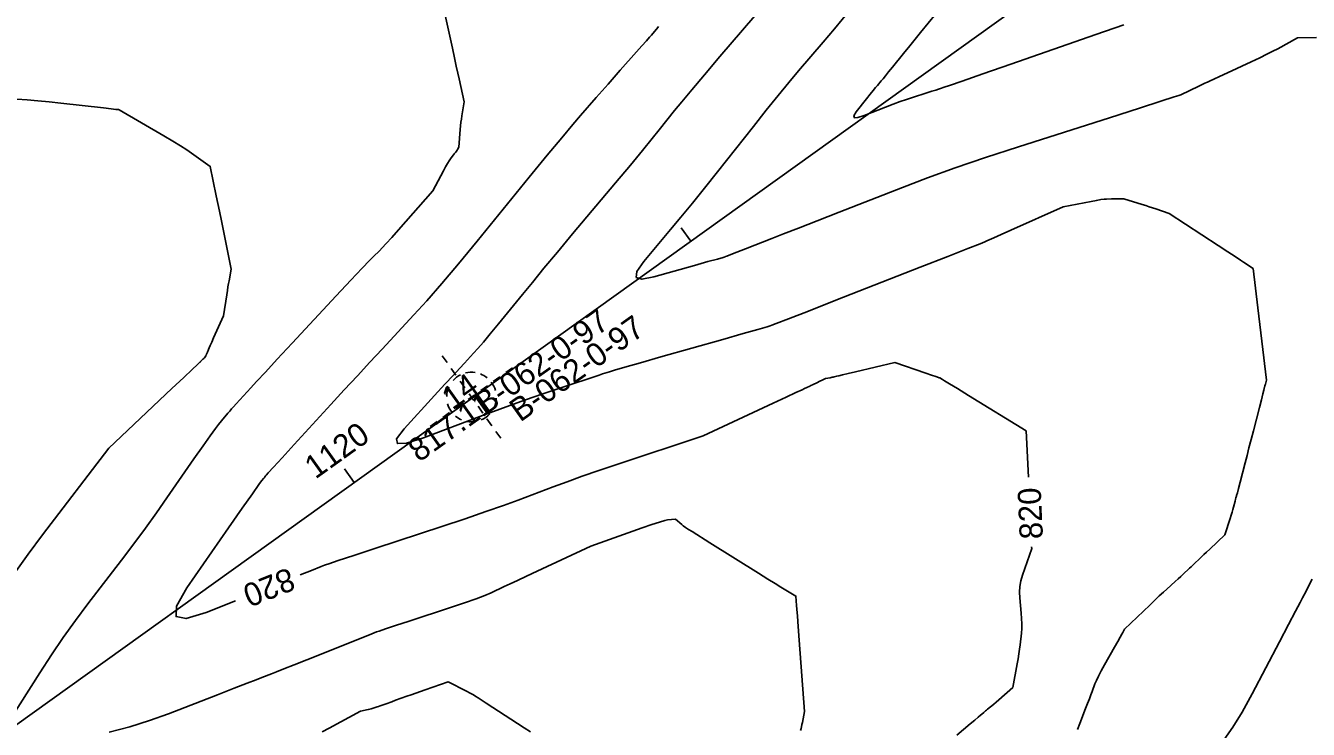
# Model space of a CAD drawing. Extents: x 2079879 to 2092887, y 778083 to 784051.
# Drawn here: x 2083948 to 2084103, y 780967 to 781052 of the extents above; entities that cross this region are included whole.
import ezdxf

# ---------------------------------------------------------------- set-up
doc = ezdxf.new("R2010")
doc.units = 0
for name, color, linetype in [('DT_X_Contour_Major', 7, 'Continuous'), ('DT_X_Contour_Minor', 7, 'Continuous'), ('GE_X_CL_20', 7, 'Continuous'), ('GT_Historic_Soil_Boring', 7, 'Continuous'), ('GT_Project_Text', 7, 'Continuous'), ('SV_X_Text_Comment', 7, 'Continuous'), ('SV_X_Text_Elevation', 7, 'Continuous'), ('SV_X_Text_Name', 7, 'Continuous')]:
    doc.layers.add(name, color=color, linetype=linetype)

msp = doc.modelspace()

# ---------------------------------------------------------------- linework, layer by layer
at = {"layer": 'DT_X_Contour_Major'}
for points in [[(2084024.47, 781051.89), (2084024.38, 781051.77), (2084023.62, 781050.86), (2084023.38, 781050.59), (2084023.01, 781050.16), (2084022.48, 781049.57), (2084021.82, 781048.81), (2084019.85, 781046.6), (2084019.12, 781045.77), (2084018.39, 781044.94), (2084017.67, 781044.12), (2084016.95, 781043.31), (2084015.04, 781041.14), (2084014.12, 781040.06), (2084012.78, 781038.46), (2084011.03, 781036.35), (2084008.87, 781033.71), (2084002.56, 781025.97), (2084000.31, 781023.24), (2083998.29, 781020.85), (2083996.5, 781018.79), (2083994.94, 781017.08), (2083991.1, 781012.95), (2083989.63, 781011.37), (2083988.11, 781009.72), (2083986.53, 781008.01), (2083984.9, 781006.24), (2083980.47, 781001.41), (2083979.02, 780999.83), (2083977.98, 780998.69), (2083977.34, 780998), (2083977.12, 780997.75), (2083977.07, 780997.69), (2083977.04, 780997.65), (2083976.98, 780997.59), (2083976.91, 780997.5), (2083976.81, 780997.38), (2083976.52, 780997.04), (2083976.19, 780996.59), (2083975.42, 780995.49), (2083974.2, 780993.74), (2083972.54, 780991.35), (2083967.52, 780984.12), (2083966.26, 780981.9), (2083966.22, 780980.66), (2083967.42, 780980.41), (2083969.85, 780981.14), (2083973.4, 780982.56)], [(2083981.2, 780985.68), (2083982.55, 780986.22), (2083983.72, 780986.69), (2083984.14, 780986.85), (2083984.24, 780986.9), (2083984.66, 780987.03), (2083985.8, 780987.41), (2083987.69, 780988.04), (2083990.32, 780988.9), (2083998.32, 780991.53), (2084001.14, 780992.47), (2084003.61, 780993.32), (2084005.74, 780994.06), (2084007.51, 780994.71), (2084011.76, 780996.32), (2084013.44, 780996.94), (2084015.27, 780997.59), (2084017.27, 780998.28), (2084019.43, 780999), (2084029.87, 781002.46), (2084038.31, 781006.4), (2084039.91, 781007.14), (2084041.07, 781007.69), (2084041.81, 781008.03), (2084042.12, 781008.17), (2084042.37, 781008.29), (2084042.45, 781008.33), (2084042.52, 781008.36), (2084042.56, 781008.38), (2084042.58, 781008.39), (2084042.62, 781008.41), (2084042.66, 781008.43), (2084042.75, 781008.47), (2084042.89, 781008.54), (2084043.08, 781008.64), (2084043.66, 781008.92), (2084043.86, 781009.02), (2084044.03, 781009.1), (2084044.16, 781009.16), (2084044.26, 781009.21), (2084044.65, 781009.38), (2084045.22, 781009.49), (2084045.34, 781009.52), (2084045.46, 781009.54), (2084045.58, 781009.57), (2084045.7, 781009.6), (2084046.01, 781009.68), (2084046.24, 781009.73), (2084046.69, 781009.84), (2084047.37, 781010), (2084048.27, 781010.22), (2084053.02, 781011.34), (2084056.75, 781010.05), (2084057.46, 781009.81), (2084057.96, 781009.64), (2084058.28, 781009.53), (2084058.39, 781009.49), (2084058.47, 781009.47), (2084058.77, 781009.28), (2084059.01, 781009.13), (2084059.61, 781008.76), (2084060.58, 781008.17), (2084061.9, 781007.36), (2084068.89, 781003.06), (2084069.16, 780997.47)], [(2084069.54, 780989.08), (2084069.55, 780988.86), (2084068.44, 780985.66), (2084068.24, 780984.98), (2084068.12, 780984.29), (2084068.07, 780983.6), (2084068.1, 780982.92), (2084068.28, 780981.08), (2084068.33, 780980.41), (2084068.35, 780979.78), (2084068.34, 780979.2), (2084068.3, 780978.65), (2084068.16, 780977.24), (2084068.09, 780976.71), (2084068.01, 780976.15), (2084067.92, 780975.56), (2084067.81, 780974.96), (2084067.26, 780972.1), (2084065.58, 780970.62), (2084065.25, 780970.33), (2084064.97, 780970.09), (2084064.75, 780969.9), (2084064.59, 780969.76), (2084064.22, 780969.46), (2084064.09, 780969.36), (2084063.97, 780969.26), (2084063.86, 780969.17), (2084063.76, 780969.09), (2084063.51, 780968.89), (2084063.35, 780968.76), (2084063.07, 780968.51), (2084062.66, 780968.16), (2084062.12, 780967.7), (2084060.51, 780966.33)]]:
    msp.add_lwpolyline(points, dxfattribs=at)
at = {"layer": 'DT_X_Contour_Minor'}
for points in [[(2083998.32, 781055.1), (2083999.58, 781049.26), (2083999.83, 781048.1), (2084000.04, 781047.09), (2084000.23, 781046.25), (2084000.38, 781045.57), (2084000.99, 781042.78), (2084000.72, 781041.1), (2084000.67, 781040.72), (2084000.62, 781040.33), (2084000.57, 781039.91), (2084000.53, 781039.47), (2084000.36, 781037.34), (2084000.2, 781037.05), (2084000.15, 781036.97), (2084000.07, 781036.85), (2083999.95, 781036.69), (2083999.81, 781036.5), (2083999.37, 781035.93), (2083999.2, 781035.68), (2083998.99, 781035.35), (2083998.76, 781034.94), (2083998.5, 781034.46), (2083997.2, 781032.05), (2083993.06, 781027.33), (2083992.25, 781026.41), (2083991.6, 781025.68), (2083991.1, 781025.15), (2083990.76, 781024.8), (2083990.07, 781024.14), (2083989.59, 781023.66), (2083988.68, 781022.7), (2083987.33, 781021.27), (2083985.56, 781019.36), (2083980.24, 781013.65), (2083978.43, 781011.71), (2083977, 781010.17), (2083975.93, 781009.02), (2083975.25, 781008.28), (2083973.91, 781006.82), (2083973.47, 781006.33), (2083973.13, 781005.97), (2083972.92, 781005.73), (2083972.81, 781005.61), (2083972.69, 781005.46), (2083972.61, 781005.37), (2083972.48, 781005.22), (2083972.3, 781005), (2083972.06, 781004.71), (2083971.35, 781003.86), (2083970.96, 781003.36), (2083970.33, 781002.49), (2083969.47, 781001.27), (2083968.36, 780999.69), (2083965.09, 780994.98), (2083963.83, 780993.18), (2083962.5, 780991.34), (2083961.09, 780989.44), (2083959.61, 780987.48), (2083955.56, 780982.19), (2083954.06, 780980.19), (2083952.59, 780978.13), (2083951.16, 780976.02), (2083949.76, 780973.86), (2083946.07, 780968.04)], [(2084037.35, 781054.64), (2084031.89, 781048.27), (2084030.02, 781046.07), (2084028.48, 781044.24), (2084027.28, 781042.8), (2084026.42, 781041.74), (2084024.57, 781039.41), (2084023.72, 781038.35), (2084022.56, 781036.93), (2084021.08, 781035.16), (2084019.29, 781033.02), (2084014.1, 781026.84), (2084012.27, 781024.65), (2084010.64, 781022.7), (2084009.24, 781021), (2084008.05, 781019.55), (2084005.16, 781016.01), (2084004.16, 781014.8), (2084003.33, 781013.8), (2084002.66, 781013.02), (2084002.15, 781012.45), (2084001.03, 781011.25), (2084000.48, 781010.66), (2083999.7, 781009.81), (2083998.68, 781008.7), (2083997.42, 781007.33), (2083993.74, 781003.32), (2083992.85, 781002.12), (2083992.95, 781001.54), (2083994.03, 781001.58), (2083996.09, 781002.24), (2084002.9, 781004.8), (2084005.31, 781005.7), (2084007.42, 781006.47), (2084009.23, 781007.12), (2084010.74, 781007.63), (2084014.38, 781008.84), (2084015.62, 781009.25), (2084016.59, 781009.57), (2084017.29, 781009.8), (2084017.73, 781009.95), (2084018.55, 781010.22), (2084019.17, 781010.4), (2084020.41, 781010.77), (2084022.28, 781011.3), (2084024.77, 781012.01), (2084032.25, 781014.12), (2084034.71, 781014.82), (2084036.48, 781015.33), (2084037.58, 781015.64), (2084037.98, 781015.76), (2084038.16, 781015.82), (2084038.69, 781016.03), (2084040.16, 781016.6), (2084042.57, 781017.54), (2084045.91, 781018.85), (2084056.07, 781022.82), (2084059.41, 781024.13), (2084061.83, 781025.08), (2084063.32, 781025.67), (2084063.88, 781025.89), (2084064.14, 781026.02), (2084064.4, 781026.14), (2084064.97, 781026.39), (2084065.85, 781026.78), (2084067.04, 781027.31), (2084073.36, 781030.1), (2084076.72, 781030.77), (2084077.37, 781030.9), (2084077.9, 781030.99), (2084078.31, 781031.04), (2084078.59, 781031.06), (2084079.17, 781031.07), (2084079.38, 781031.08), (2084079.57, 781031.08), (2084079.76, 781031.08), (2084079.92, 781031.09), (2084080.66, 781031.1), (2084082.87, 781030.42), (2084083.33, 781030.27), (2084083.75, 781030.13), (2084084.15, 781030), (2084084.52, 781029.88), (2084086.15, 781029.3), (2084092.08, 781025.44), (2084093.23, 781024.69), (2084094.11, 781024.11), (2084094.75, 781023.7), (2084095.12, 781023.45), (2084096.28, 781022.67), (2084096.84, 781017.94), (2084096.96, 781016.93), (2084097.09, 781015.92), (2084097.21, 781014.91), (2084097.33, 781013.9), (2084097.91, 781009.19), (2084097.77, 781008.72), (2084097.74, 781008.62), (2084097.71, 781008.53), (2084097.69, 781008.44), (2084097.68, 781008.37), (2084097.64, 781008.18), (2084097.59, 781007.98), (2084097.48, 781007.53), (2084097.3, 781006.84), (2084097.05, 781005.9), (2084096.32, 781003.06), (2084096.05, 781002.02), (2084095.79, 781001.03), (2084095.55, 781000.09), (2084095.32, 780999.2), (2084094.73, 780996.89), (2084094.53, 780996.13), (2084094.39, 780995.59), (2084094.3, 780995.26), (2084094.27, 780995.15), (2084094.26, 780995.14), (2084094.24, 780995.1), (2084094.21, 780995), (2084094.17, 780994.82), (2084094.11, 780994.59), (2084093.93, 780993.86), (2084093.85, 780993.57), (2084093.76, 780993.24), (2084093.65, 780992.88), (2084093.52, 780992.48), (2084092.88, 780990.52), (2084091.04, 780988.79), (2084090.67, 780988.44), (2084090.34, 780988.13), (2084090.05, 780987.86), (2084089.81, 780987.63), (2084089.21, 780987.06), (2084088.99, 780986.86), (2084088.79, 780986.67), (2084088.6, 780986.49), (2084088.43, 780986.33), (2084087.98, 780985.91), (2084087.79, 780985.73), (2084087.54, 780985.5), (2084087.24, 780985.22), (2084086.88, 780984.9), (2084085.86, 780983.97), (2084085.45, 780983.59), (2084084.96, 780983.14), (2084084.41, 780982.62), (2084083.8, 780982.03), (2084080.77, 780979.14), (2084080.54, 780978.72), (2084080.44, 780978.54), (2084080.24, 780978.18), (2084079.94, 780977.66), (2084079.54, 780976.95), (2084078.35, 780974.84), (2084077.95, 780974.1), (2084077.62, 780973.47), (2084077.37, 780972.95), (2084077.19, 780972.55), (2084076.83, 780971.6), (2084076.69, 780971.2), (2084076.51, 780970.73), (2084076.3, 780970.17), (2084076.05, 780969.54), (2084075.37, 780967.74), (2084075.08, 780967.01)], [(2084047.6, 781053.86), (2084045.73, 781051.6), (2084044.36, 781049.98), (2084041.4, 781046.52), (2084040.23, 781045.13), (2084038.92, 781043.55), (2084037.49, 781041.78), (2084035.93, 781039.82), (2084031.6, 781034.36), (2084030.03, 781032.38), (2084028.56, 781030.56), (2084027.19, 781028.89), (2084025.93, 781027.37), (2084022.69, 781023.51), (2084021.86, 781022.31), (2084021.79, 781021.6), (2084022.48, 781021.38), (2084023.93, 781021.66), (2084028.82, 781023.04), (2084030.43, 781023.5), (2084031.58, 781023.82), (2084032.28, 781024.02), (2084032.52, 781024.09), (2084032.57, 781024.11), (2084032.74, 781024.17), (2084033.2, 781024.35), (2084033.95, 781024.65), (2084034.99, 781025.06), (2084038.17, 781026.3), (2084039.57, 781026.85), (2084041.4, 781027.56), (2084043.64, 781028.43), (2084046.3, 781029.48), (2084053.95, 781032.47), (2084056.98, 781033.62), (2084060.32, 781034.81), (2084063.97, 781036.06), (2084067.94, 781037.36), (2084078.94, 781040.88), (2084082.56, 781042.04), (2084085.16, 781042.88), (2084086.74, 781043.38), (2084087.31, 781043.56), (2084087.57, 781043.65), (2084089.72, 781044.68), (2084090.13, 781044.88), (2084090.44, 781045.03), (2084090.65, 781045.13), (2084090.76, 781045.18), (2084090.92, 781045.26), (2084091.11, 781045.34), (2084091.55, 781045.55), (2084092.24, 781045.87), (2084093.2, 781046.31), (2084096.07, 781047.64), (2084097.08, 781048.12), (2084097.95, 781048.54), (2084098.67, 781048.9), (2084099.26, 781049.21), (2084101.66, 781050.52), (2084103.93, 781050.58)], [(2084057.96, 781053.41), (2084056.13, 781051.15), (2084054.83, 781049.55), (2084054.07, 781048.61), (2084052.73, 781046.97), (2084052.27, 781046.4), (2084051.9, 781045.94), (2084051.6, 781045.58), (2084051.38, 781045.33), (2084050.91, 781044.78), (2084050.7, 781044.52), (2084050.41, 781044.17), (2084050.05, 781043.72), (2084049.61, 781043.17), (2084048.36, 781041.58), (2084048.06, 781041.11), (2084048.13, 781040.88), (2084048.55, 781040.89), (2084049.33, 781041.14), (2084051.9, 781042.15), (2084052.82, 781042.5), (2084053.66, 781042.82), (2084054.43, 781043.09), (2084055.13, 781043.32), (2084056.88, 781043.88), (2084057.47, 781044.07), (2084057.95, 781044.22), (2084058.3, 781044.33), (2084058.53, 781044.41), (2084058.98, 781044.55), (2084059.61, 781044.77), (2084061.16, 781045.3), (2084063.63, 781046.16), (2084067.02, 781047.34), (2084077.29, 781050.91), (2084080.67, 781052.08)], [(2083946.98, 781043.11), (2083948.21, 781043.03), (2083949.51, 781042.93), (2083950.87, 781042.8), (2083952.29, 781042.65), (2083957.44, 781042.05), (2083958.36, 781041.95), (2083958.92, 781041.88), (2083959.12, 781041.86), (2083959.17, 781041.85), (2083959.19, 781041.85), (2083959.21, 781041.85), (2083959.22, 781041.85), (2083959.24, 781041.85), (2083959.32, 781041.84), (2083964.75, 781038.67), (2083965.83, 781038.03), (2083966.75, 781037.47), (2083967.49, 781037), (2083968.06, 781036.61), (2083970.34, 781035), (2083971.06, 781031.46), (2083971.44, 781029.6), (2083971.68, 781028.43), (2083972.87, 781022.59), (2083972.61, 781021.2), (2083972.55, 781020.87), (2083972.48, 781020.48), (2083972.41, 781020.02), (2083972.33, 781019.51), (2083971.95, 781016.96), (2083970.74, 781014.29), (2083970.51, 781013.78), (2083970.33, 781013.38), (2083970.2, 781013.09), (2083970.13, 781012.91), (2083970, 781012.59), (2083969.96, 781012.48), (2083969.93, 781012.4), (2083969.9, 781012.34), (2083969.89, 781012.31), (2083969.86, 781012.25), (2083969.85, 781012.22), (2083969.83, 781012.2), (2083969.82, 781012.17), (2083969.8, 781012.14), (2083969.73, 781012.01), (2083969.63, 781011.9), (2083969.61, 781011.87), (2083969.57, 781011.83), (2083969.51, 781011.78), (2083969.45, 781011.72), (2083969.21, 781011.48), (2083969.17, 781011.44), (2083969.14, 781011.42), (2083969.13, 781011.41), (2083969.12, 781011.4), (2083969.11, 781011.39), (2083969.1, 781011.38), (2083969.09, 781011.37), (2083969.07, 781011.35), (2083968.79, 781011.08), (2083968.16, 781010.49), (2083967.13, 781009.53), (2083965.7, 781008.18), (2083958.1, 781001), (2083950.08, 780990.53), (2083948.34, 780988.19), (2083946.54, 780985.65)], [(2083958.13, 780966.69), (2083960.61, 780967.35), (2083962.99, 780968.09), (2083965.28, 780968.91), (2083971.23, 780971.22), (2083973.24, 780972), (2083974.8, 780972.6), (2083975.9, 780973.03), (2083976.56, 780973.29), (2083977.72, 780973.74), (2083978.32, 780973.97), (2083979.23, 780974.33), (2083980.46, 780974.82), (2083982, 780975.44), (2083986.54, 780977.26), (2083988.05, 780977.86), (2083989.15, 780978.3), (2083989.85, 780978.58), (2083990.15, 780978.7), (2083990.42, 780978.8), (2083990.74, 780978.91), (2083991.51, 780979.16), (2083992.71, 780979.56), (2083994.36, 780980.11), (2083999.34, 780981.75), (2084001.05, 780982.32), (2084002.44, 780982.81), (2084003.51, 780983.21), (2084004.26, 780983.53), (2084005.85, 780984.27), (2084006.55, 780984.59), (2084007.44, 780985.01), (2084008.53, 780985.52), (2084009.82, 780986.12), (2084016.29, 780989.14), (2084022.49, 780991.35), (2084023.68, 780991.77), (2084024.59, 780992.07), (2084025.22, 780992.26), (2084025.56, 780992.33), (2084026.52, 780992.4), (2084027.28, 780991.76), (2084027.47, 780991.61), (2084027.75, 780991.41), (2084028.1, 780991.18), (2084028.52, 780990.91), (2084030.68, 780989.55), (2084036.54, 780985.89), (2084037.67, 780985.18), (2084038.57, 780984.63), (2084039.23, 780984.22), (2084039.66, 780983.96), (2084041.07, 780983.13), (2084041.15, 780981.99), (2084041.19, 780981.55), (2084041.25, 780980.7), (2084041.34, 780979.46), (2084041.46, 780977.81), (2084042.11, 780969.19), (2084041.85, 780967.88), (2084041.79, 780967.61), (2084041.74, 780967.36), (2084041.69, 780967.13), (2084041.64, 780966.91)], [(2084103.43, 780985.17), (2084102.95, 780984.24), (2084102.68, 780983.73), (2084102.26, 780982.92), (2084101.97, 780982.36), (2084101.4, 780981.29), (2084100.57, 780979.7), (2084099.47, 780977.6), (2084096.17, 780971.31), (2084094.97, 780969.13), (2084093.84, 780967.29), (2084092.78, 780965.8)], [(2083983.86, 780966.76), (2083984.69, 780967.2), (2083988.48, 780969.24), (2083989.41, 780969.43), (2083989.6, 780969.47), (2083989.76, 780969.51), (2083989.9, 780969.54), (2083990.01, 780969.58), (2083990.27, 780969.67), (2083990.51, 780969.76), (2083990.66, 780969.81), (2083990.84, 780969.87), (2083991.34, 780970.05), (2083991.57, 780970.14), (2083992.26, 780970.38), (2083992.73, 780970.55), (2083994.09, 780971.04), (2083994.61, 780971.22), (2083995.15, 780971.41), (2083995.72, 780971.61), (2083996.3, 780971.81), (2083999.08, 780972.79), (2084001.3, 780971.64), (2084001.74, 780971.41), (2084002.12, 780971.2), (2084002.43, 780971.02), (2084002.68, 780970.86), (2084003.67, 780970.19), (2084007.46, 780967.75), (2084008.26, 780967.24), (2084009.03, 780966.74)]]:
    msp.add_lwpolyline(points, dxfattribs=at)
at = {"layer": 'GE_X_CL_20'}
for p, q in [((2079923.52, 778084.44), (2085691.45, 782217.74)), ((2084028.37, 781025.98), (2084027.21, 781027.6)), ((2083987.73, 780996.85), (2083986.57, 780998.48))]:
    msp.add_line(p, q, dxfattribs=at)
at = {"layer": 'GT_Historic_Soil_Boring'}
for p, q in [((2083998.93, 781011.31), (2083998.35, 781012.13)), ((2084000.01, 781009.79), (2083999.43, 781010.6)), ((2084006.04, 781010.11), (2084006.86, 781010.69)), ((2084001.09, 781008.27), (2084000.52, 781009.08)), ((2084004.52, 781009.03), (2084005.33, 781009.61)), ((2084001.48, 781006.87), (2084002.29, 781007.44)), ((2084002.17, 781006.75), (2084001.6, 781007.56)), ((2084003, 781007.95), (2084003.81, 781008.52)), ((2083999.96, 781005.78), (2084000.77, 781006.36)), ((2084003.26, 781005.23), (2084002.68, 781006.04)), ((2083996.91, 781003.62), (2083997.73, 781004.2)), ((2083998.43, 781004.7), (2083999.25, 781005.28)), ((2084004.34, 781003.7), (2084003.76, 781004.52)), ((2084005.42, 781002.18), (2084004.84, 781003))]:
    msp.add_line(p, q, dxfattribs=at)
for start, end in [(116.1004, 137.8542), (81.7763, 103.8478), (50.5725, 69.1485), (15.3912, 37.2663), (155.2403, 178.2725), (195.4001, 217.525), (336.0857, 357.4228), (230.117, 246.0621), (259.8922, 279.0649), (293.2752, 317.3154)]:
    msp.add_arc((2084001.89, 781007.15), 3, start, end, dxfattribs=at)

# ---------------------------------------------------------------- texts
at = {"layer": 'DT_X_Contour_Major'}
for rotation, p in [(92.5677, (2084070.91, 780990.05)), (201.8182, (2083979.83, 780986.64))]:
    msp.add_text('820', height=2.8, rotation=rotation, dxfattribs=at).set_placement(p)
at = {"layer": 'GE_X_CL_20'}
msp.add_text('1120', height=2.8, rotation=35.6254, dxfattribs=at).set_placement((2083983.04, 780997.18))
at = {"layer": 'GT_Project_Text'}
msp.add_text('B-062-0-97', height=2.8, rotation=35.3935, dxfattribs=at).set_placement((2084007.77, 781004.06))
at = {"layer": 'SV_X_Text_Comment'}
msp.add_text('B-062-0-97', height=2.8, rotation=35.3935, dxfattribs=at).set_placement((2084003.51, 781004.87))
at = {"layer": 'SV_X_Text_Elevation'}
msp.add_text('817.11', height=2.8, rotation=35.3935, dxfattribs=at).set_placement((2083995.55, 780999.22))
at = {"layer": 'SV_X_Text_Name'}
msp.add_text('14', height=2.8, rotation=35.3935, dxfattribs=at).set_placement((2083999.59, 781005.52))

doc.saveas('drawing.dxf')
